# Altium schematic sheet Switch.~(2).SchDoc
size A
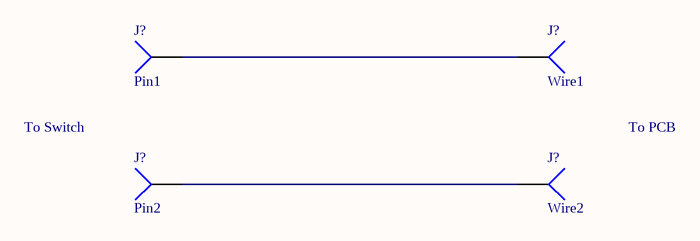
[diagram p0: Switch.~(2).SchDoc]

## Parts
(Parts that share a designator on the sheet are numbered #1, #2 ... from top to bottom, then left to right.)
J?#1  Pin1  [PIN1]
J?#2  Wire1  [PIN1]
J?#3  Pin2  [PIN1]
J?#4  Wire2  [PIN1]

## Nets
NetJ?#1_1: J?#1.1 J?#2.1
NetJ?#3_1: J?#3.1 J?#4.1

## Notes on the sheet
- To Switch
- To PCB

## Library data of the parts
J?#1-J?#4 = Socket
